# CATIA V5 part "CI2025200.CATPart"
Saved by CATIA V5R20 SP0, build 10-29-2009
Part number: CI2025200
Bounding box of the stored display mesh (mm): x -24 to 24, y -18.97 to 234.5, z -32.903 to 26.909
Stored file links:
  C:\Users\Raffaele\Desktop\3D X SITO CF\BOLEX\19-INCLINED ASSEMBLY REF_CI\CI2025200.CATPart

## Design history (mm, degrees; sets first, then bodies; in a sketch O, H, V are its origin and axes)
Set1
  DatumSurface1 to DatumSurface16 "MANIFOLD_SOLID_BREP #393"
  DatumSurface17 to DatumSurface39 "MANIFOLD_SOLID_BREP #1138"
Body1 (main body)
